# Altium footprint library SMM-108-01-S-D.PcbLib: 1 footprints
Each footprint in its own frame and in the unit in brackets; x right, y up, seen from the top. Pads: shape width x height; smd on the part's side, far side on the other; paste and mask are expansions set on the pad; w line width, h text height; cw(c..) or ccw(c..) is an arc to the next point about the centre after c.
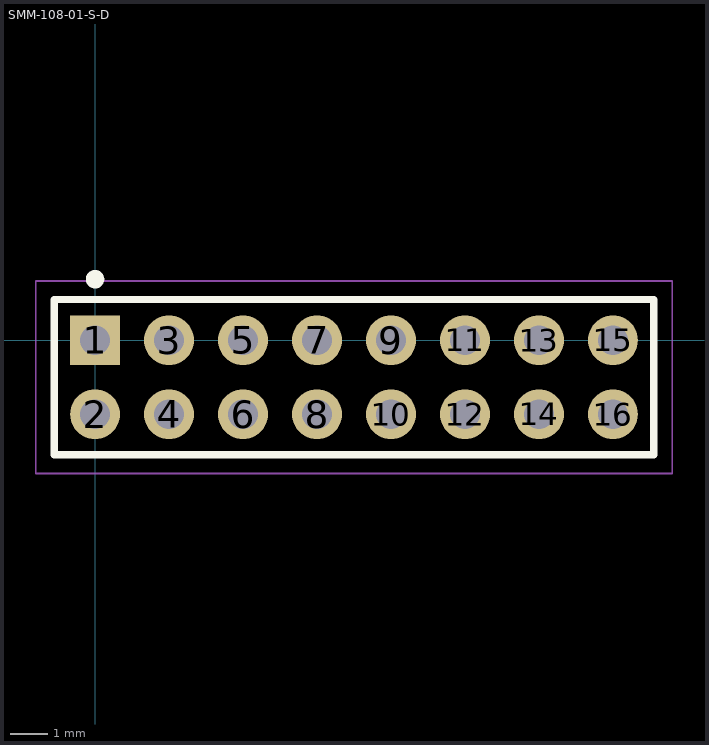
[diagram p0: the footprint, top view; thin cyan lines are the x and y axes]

## SMM-108-01-S-D [mm] "2.00mm pitch, 16 pin, socket strip; double row, PTH"
height 3.56
pads (16):
  rect 1.35x1.35 / inner round 1.35 / far side rect 1.35x1.35 hole 0.8 mask+0: 1(0,0)
  round 1.35 hole 0.8 mask+0: 2(0,-2) 3(2,0) 4(2,-2) 5(4,0) 6(4,-2) 7(6,0) 8(6,-2) 9(8,0) 10(8,-2) 11(10,0) 12(10,-2) 13(12,0) 14(12,-2) 15(14,0) 16(14,-2)
Top Overlay:
  circle w0.25: c0,1.65 r0.125
  lines w0.2: -1.1,-3.1 -1.1,1.1 15.1,1.1 15.1,-3.1 -1.1,-3.1
Mechanical 12:
  lines w0.001: -1.1,-3.1 -1.1,1.1 15.1,1.1 15.1,-3.1 -1.1,-3.1
Mechanical 13:
  circle w0.1: c0,1.65 r0.125
  lines w0.1: -1.1,-3.1 -1.1,1.1 15.1,1.1 15.1,-3.1 -1.1,-3.1
  text ".Designator" at 0,-0.127 h1.52
Mechanical 15:
  lines w0.05: -1.6,-3.6 -1.6,1.6 15.6,1.6 15.6,-3.6 -1.6,-3.6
